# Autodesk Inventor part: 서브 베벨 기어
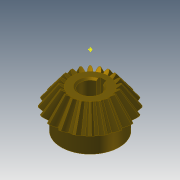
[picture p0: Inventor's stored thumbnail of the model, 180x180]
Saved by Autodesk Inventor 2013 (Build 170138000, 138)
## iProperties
Created: 2014-10
Part Number: 서브 베벨 기어
Material: 강철
Document SubType Name: Modeling
Designer: KYOUNG IL JANG
Categories: <?xml version="1.0" encoding="UTF-16"?> <MemberInstance><Categories><FamilyTemplate><FamilyTemplateParameter ValueType="xs:double" Id="1" ObjectReferenceKey="da
Mass: 134.694 g
Surface Area: 63.6518 cm^2
Volume: 17.1585 cm^3
Density: 7.85 g/cm^3
CustomPartVersion: 1
Company: 한국ATC센터
Author: KYOUNG IL JANG
Revision Number: 1
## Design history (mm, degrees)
node "맨 위 점"
node "메쉬 평면2"
sketch "톱니 본체 스케치"
  geometry: L1 (0, 0)-(18.003, -31.331); L2 (18.003, -31.331)-(21.664, -28.891); L3 (21.664, -28.891)-(0, 0); L4 (20, -30)-(0, 0); L5 (10.813, -18.818)-(13.012, -17.352); L6 (18.003, -31.331)-(10.813, -18.818); L7 (21.664, -28.891)-(13.012, -17.352); L8 (0, -39.387)-(0, 6.564) reference; L9 (0, -30)-(21.664, -30)
  constraints: 16 end point, 4 point on line, 3 perpendicular, 2 collinear, 1 horizontal alignment, 1 vertical alignment
  dimensions: "d0" = 40 diameter of L4.start L8 (= da_de); "d1" = 36.00616 diameter of L1.end L8 (= da_dfe); "d2" = 43.3282 diameter of L2.end L8 (= da_dae); "d3" = 14.4 distance between parallel lines of L2 L5 (= da_b); "d4" = 28.8906 vertical distance of L2.end L1.start (= da_ve)
revolve "톱니 본체" sketch "톱니 본체 스케치" stored, may be unused: angle "d5" = 90 deg
node "시작점"
node "톱니 평면"
sketch "시작 스케치"
  geometry: L1 (0, -23.505)-(0, 10.645) reference; L2 (-0.834, -2.928)-(0.834, -2.928); A1 r 8.898 centre (-9.698, -3.713) between (-0.834, -2.928) and (-3.903, 3.04); A2 r 8.898 centre (9.698, -3.713) between (3.903, 3.04) and (0.834, -2.928); A3 r 27.357 centre (0, -24.037) between (3.903, 3.04) and (-3.903, 3.04); 1 further point
  constraints: 6 point on circle, 3 centre point, 3 symmetric about line, 2 end point, 1 coincident, 1 perpendicular, 1 other
  dimensions: "d7" = 8.89846 radius of A1 (= fd_rr); "d8" = 9.69794 horizontal distance of point (0, -24.037) A1.centre (= fd_x); "d9" = 20.32439 vertical distance of point (0, -24.037) A1.centre (= fd_y); "d57" = 27.35701 radius of A3 (= 0.5 x fd_dva + 0.3 x da_he); "d58" = 21.10901 distance from line of A3.centre L2 (= 0.5 x fd_dva - 1.12 x da_he)
node "끝점"
  node "끝 평면"
sketch "3D 스케치 오른쪽"
  node "Helical Curve Right" dims "d65" = 229.90621 (computed from da_dm, da_delta, da_beta), "d66" = 31.5, "d67" = 40 (= da_de), "d68" = -5.88003 (= -da_delta), "d69" = 12.16458 (computed from fd_loft, da_delta)
node "끝 평면 오른쪽"
sketch "끝 스케치 오른쪽"
  geometry: L1 (0, -22.649)-(0, 12.15) reference; L2 (-0.497, -1.72)-(0.497, -1.72); A1 r 5.299 centre (-5.775, -2.187) between (-0.497, -1.72) and (-2.324, 1.834); A2 r 5.299 centre (5.775, -2.187) between (2.324, 1.834) and (0.497, -1.72); A3 r 16.291 centre (0, -14.29) between (2.324, 1.834) and (-2.324, 1.834); 1 further point
  constraints: 6 point on circle, 3 centre point, 3 symmetric about line, 2 end point, 1 coincident, 1 perpendicular, 1 other
  dimensions: "d70" = 5.77526 horizontal distance of A3.centre A1.centre (computed from fd_x, fd_ratio); "d71" = 12.10346 vertical distance of point (0, -14.29) A1.centre (computed from fd_y, fd_ratio); "d72" = 5.29916 radius of A1 (computed from fd_rr, fd_ratio); "d73" = 12.57071 distance from line of point (0, -14.29) L2 (computed from d58, fd_ratio); "d74" = 16.29149 radius of A3 (computed from d57, fd_ratio)
feature "로프트 오른쪽" sketch "끝 스케치 오른쪽" dims "d75" = 0, "d77" = 0, "d79" = 0, "d80" = 90 deg, "d85" = 20, "d92" = 90 deg, "d93" = 90 deg, "da_teethtype" = 0 [user parameter]
sketch "3D 스케치 왼쪽"
  node "Helical Curve Left" dims "d26" = 229.90621 (computed from da_dm, da_delta, da_beta), "d27" = 12.16458 (computed from fd_loft, da_delta), "d28" = 40 (= da_de), "d29" = -5.88003 (= -da_delta)
node "끝 평면 왼쪽"
sketch "끝 스케치 왼쪽" dims "d56" = 10.82768 (derived)
  geometry: L1 (0, -35.087)-(0, 18.089) reference; L2 (-0.497, -1.716)-(0.497, -1.716); A1 r 5.299 centre (-5.775, -2.183) between (-0.497, -1.716) and (-2.324, 1.838); A2 r 5.299 centre (5.775, -2.183) between (2.324, 1.838) and (0.497, -1.716); A3 r 16.291 centre (0, -14.287) between (2.324, 1.838) and (-2.324, 1.838); 2 further points; 1 other entity
  constraints: 6 point on circle, 3 centre point, 3 symmetric about line, 2 end point, 1 coincident, 2 other
  dimensions: "d30" = 5.29916 radius of A1 (computed from fd_rr, fd_ratio); "d31" = 5.77526 horizontal distance of point (0, -14.287) A1.centre (computed from fd_x, fd_ratio); "d32" = 12.10346 vertical distance of A1.centre point (0, -14.287) (computed from fd_y, fd_ratio); "d61" = 16.29149 radius of A3 (computed from d57, fd_ratio); "d62" = 12.57071 distance from line of point (0, -14.287) L2 (computed from d58, fd_ratio)
feature "로프트 왼쪽" sketch "끝 스케치 왼쪽" dims "d35" = 0, "d37" = 0, "d39" = 0, "d40" = 90 deg, "d84" = 10, "d90" = 90 deg, "d91" = 90 deg, "da_teethtype" = 0 [user parameter]
sketch "본체 스케치"
  geometry: L1 (0, -35.038)-(0, -19.531) reference; L2 (18.003, -31.331)-(10.813, -18.818) reference; L3 (10.813, -18.818)-(0, -18.818); L4 (18.003, -31.331)-(0, -31.331)
  constraints: 4 end point, 2 perpendicular, 2 point on line
revolve "본체 고정" sketch "본체 스케치" stored, may be unused: angle "d46" = 90 deg
feature "피치 지름" dims angle "d47" = 90 deg
sketch "스케치8"
  geometry: C1 r 17 at (0, 0); 1 further point
  constraints: 1 centre point, 1 coincident
  dimensions: "d94" = 34 diameter of C1
extrude "돌출1" join sketch "스케치8" distance "d95" = 10; taper "d96" = 0 deg
sketch "스케치9"
  geometry: 1 further point
hole "구멍1" sketch "스케치9" at (0, 0) diameter "d97" = 12; stored, may be unused: countersink angle "d101" = 90 deg, drill point angle "d103" = 118 deg; dims "d98" = 6, "d99" = 4, "d100" = 2, "d102" = 8
sketch "스케치10"
  geometry: 1 further point
sketch "스케치11"
  geometry: 1 further point
sketch "스케치12"
  geometry: L1 (-2, 5.657)-(-2, 7.8); L2 (-2, 7.8)-(2, 7.8); L3 (2, 7.8)-(2, 5.657); A1 r 6 centre (0, 0) between (-2, 5.657) and (2, 5.657) reference; 1 further point
  constraints: 6 end point, 2 parallel, 2 point on circle, 1 perpendicular, 1 vertical
  dimensions: "d104" = 4 distance of L1.end L2.end; "d105" = 13.8 dimension on A1 L2
extrude "돌출2" cut sketch "스케치12" stored distance "d106" = 7; taper "d107" = 0 deg
chamfer "모따기1" distance "d108" = 1; stored, may be unused: second distance "d109" = 2, angle "d110" = 45 deg
body "Solid1"
feature "로프트" dims "d17" = 0, "d18" = 90 deg, "d19" = 0, "d20" = 90 deg, "d89" = 0, "da_teethtype" = 0 [user parameter]
pattern_circular "원형 패턴" dims angle "d22" = 360 deg, "d88" = 0, "da_teethtype" = 0 [user parameter]
pattern_circular "원형 패턴 오른쪽" dims angle "d82" = 360 deg, "da_teethtype" = 0 [user parameter]
pattern_circular "원형 패턴 왼쪽" dims angle "d42" = 360 deg, "da_teethtype" = 0 [user parameter]
sketch "끝 스케치"
  geometry: L1 (0, -15.359)-(0, 6.983) reference; L2 (-0.497, -1.72)-(0.497, -1.72); A1 r 5.299 centre (-5.775, -2.187) between (-0.497, -1.72) and (-2.324, 1.834); A2 r 5.299 centre (5.775, -2.187) between (2.324, 1.834) and (0.497, -1.72); A3 r 16.291 centre (0, -14.29) between (2.324, 1.834) and (-2.324, 1.834); 1 further point
  constraints: 6 point on circle, 3 centre point, 3 symmetric about line, 2 end point, 1 coincident, 1 other
  dimensions: "d12" = 5.29916 radius of A1 (computed from fd_rr, fd_ratio); "d15" = 5.77526 horizontal distance of A1.centre point (0, -14.29) (computed from fd_x, fd_ratio); "d16" = 12.10346 vertical distance of A1.centre point (0, -14.29) (computed from fd_y, fd_ratio); "d59" = 16.29149 radius of A3 (computed from d57, fd_ratio); "d60" = 12.57071 distance from line of A3.centre L2 (computed from d58, fd_ratio)
sketch "Sketch6"
  geometry: L1 (20, -30)-(0, 0) reference; L2 (0, -37.8)-(0, 6.3) reference
body "Srf1"
other parameters: "da_b" = 14.4 [user parameter; used in 2 equation terms], "da_de" = 40 [user parameter; used in 4 equation terms], "da_dae" = 43.3282 [user parameter; used in 2 equation terms], "da_dfe" = 36.00616 [user parameter; used in 1 equation term], "da_le" = 36.05551 [user parameter; used in 1 equation term], "da_omega" = 90 deg [user parameter; used in 1 equation term], "da_beta" = 0 [user parameter; used in 2 equation terms], "da_delta" = 5.88003 [user parameter; used in 8 equation terms], "da_alpha" = 20 deg [user parameter; used in 2 equation terms], "da_he" = 4.4 [user parameter; used in 4 equation terms], "da_ve" = 28.8906 [user parameter; used in 1 equation term], "fd_dv" = 48.07402 (computed from da_de, da_delta) [user parameter; used in 1 equation term], "fd_dva" = 52.07402 (computed from da_dae, da_delta) [user parameter; used in 3 equation terms], "fd_dvb" = 45.1748 (computed from fd_dv, da_alpha) [user parameter; used in 2 equation terms], "da_zv" = 240.37008 [user parameter; used in 1 equation term], "fd_loft" = 14.62 (= da_b + 0.05 x da_he) [user parameter; used in 4 equation terms], "fd_ratio" = 5.95514 (computed from da_le, fd_loft) [user parameter; used in 15 equation terms], "fd_rr" = 8.89846 (computed from fd_dd, fd_dvb) [user parameter; used in 6 equation terms], "fd_angle" = 0.66075 (computed from da_zv) [user parameter; used in 4 equation terms], "fd_x1" = 1.58709 (computed from da_dvw, fd_angle) [user parameter; used in 1 equation term], "fd_y1" = 23.98456 (computed from da_dvw, fd_angle) [user parameter; used in 1 equation term], "fd_x2" = 8.11084 (computed from fd_rr, fd_angle2, fd_angle) [user parameter; used in 1 equation term], "fd_y2" = 3.66016 (computed from fd_rr, fd_angle2, fd_angle) [user parameter; used in 1 equation term], "fd_x" = 9.69794 (= fd_x1 + fd_x2) [user parameter; used in 4 equation terms], "fd_y" = 20.32439 (= fd_y1 - fd_y2) [user parameter; used in 4 equation terms], "fd_angle2" = 3.57832 (computed from fd_dvb, fd_dd, da_alpha) [user parameter; used in 2 equation terms], "fd_dd" = 48.55402 (= fd_dva - 0.8 x da_he) [user parameter; used in 2 equation terms], "da_dvw" = 48.07402 [user parameter; used in 2 equation terms], "d11" = 14.62 (= fd_loft), "da_dm" = 32.01232 [user parameter; used in 2 equation terms], "da_x" = 0 [user parameter], "da_m" = 2 [user parameter], "d48" = 0, "d49" = 0, "d50" = 90 deg (= da_omega), "d51" = 9 deg (computed from da_z), "d52" = 0, "d53" = 0, "d54" = 0
